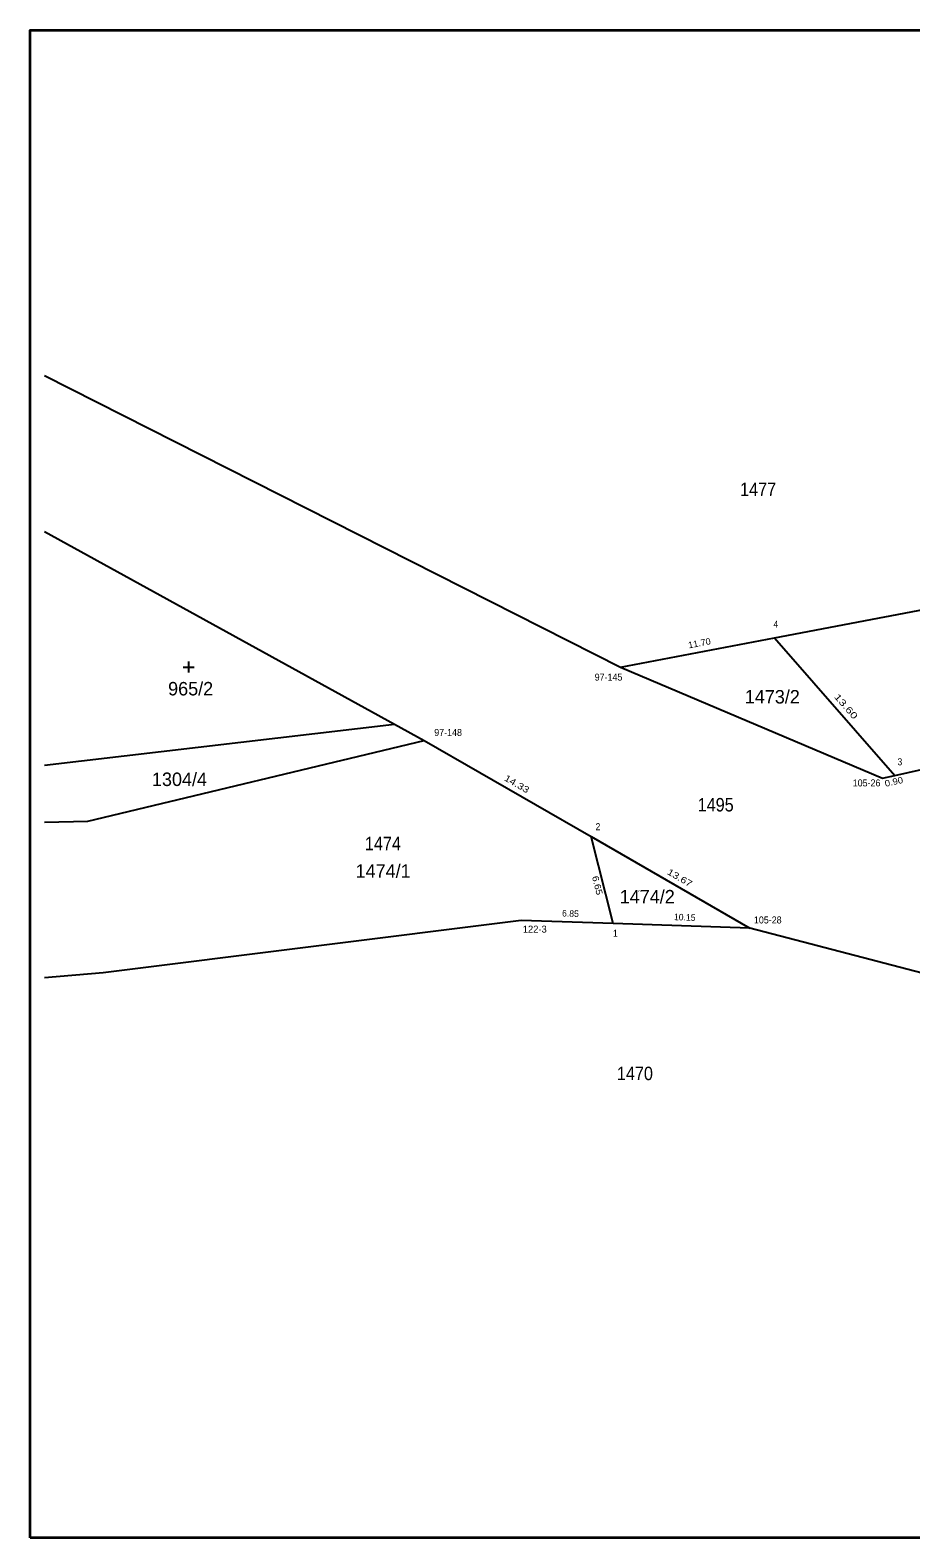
# Model space of a CAD drawing. Extents: x -871901 to -870967, y -1075952 to -1074892.
# Drawn here: x -871449.3 to -871383.9, y -1075118.4 to -1075006.4 of the extents above; entities that cross this region are included whole.
import ezdxf
from ezdxf.enums import TextEntityAlignment as Align

# ---------------------------------------------------------------- set-up
doc = ezdxf.new("R2010")
doc.units = 0
doc.header["$LTSCALE"] = 0.4
for name, color, linetype, lineweight in [('1', 7, 'Continuous', 25), ('25', 7, 'Continuous', 25), ('55', 7, 'Continuous', 35), ('62', 7, 'Continuous', 25)]:
    doc.layers.add(name, color=color, linetype=linetype, lineweight=lineweight)
doc.layers.add('18', color=7, linetype='Continuous')
doc.layers.add('54', color=7, linetype='Continuous')

msp = doc.modelspace()

# ---------------------------------------------------------------- linework, layer by layer
at = {"layer": '1'}
for p, q in [((-871448.26, -1075032.02), (-871405.48, -1075053.67)), ((-871448.26, -1075043.6), (-871422.26, -1075057.91)), ((-871405.48, -1075053.67), (-871386.01, -1075061.93)), ((-871385.08, -1075061.72), (-871352.22, -1075054.34)), ((-871448.26, -1075060.97), (-871422.26, -1075057.91)), ((-871422.26, -1075057.91), (-871420.07, -1075059.12)), ((-871445.05, -1075065.11), (-871420.07, -1075059.12)), ((-871420.07, -1075059.12), (-871407.66, -1075066.26)), ((-871386.01, -1075061.93), (-871385.08, -1075061.72)), ((-871448.26, -1075065.19), (-871445.05, -1075065.11)), ((-871407.66, -1075066.26), (-871395.86, -1075073.06)), ((-871395.86, -1075073.06), (-871406.02, -1075072.72)), ((-871380.21, -1075077.17), (-871395.86, -1075073.06))]:
    msp.add_line(p, q, dxfattribs=at)
for points in [[(-871405.48, -1075053.67), (-871394.04, -1075051.49), (-871345.38, -1075042.25)], [(-871406.02, -1075072.72), (-871412.84, -1075072.49), (-871443.91, -1075076.38), (-871448.26, -1075076.75)]]:
    msp.add_lwpolyline(points, dxfattribs=at)
at = {"layer": '25'}
for p, q in [((-871437.55, -1075054.07), (-871437.55, -1075053.269)), ((-871437.95, -1075053.669), (-871437.149, -1075053.669))]:
    msp.add_line(p, q, dxfattribs=at)
at = {"layer": '55'}
msp.add_lwpolyline([(-871449.33, -1075118.36), (-871449.33, -1075006.36), (-871287.33, -1075006.36), (-871287.33, -1075118.36)], close=True, dxfattribs=at)
at = {"layer": '62'}
for p, q in [((-871394.04, -1075051.49), (-871385.08, -1075061.72)), ((-871406.02, -1075072.72), (-871407.66, -1075066.26))]:
    msp.add_line(p, q, dxfattribs=at)

# ---------------------------------------------------------------- texts
at = {"layer": '18', "width": 0.9}
for s, p in [('1477', (-871396.59, -1075040.97)), ('1495', (-871399.74, -1075064.4)), ('1474', (-871424.46, -1075067.28)), ('1470', (-871405.74, -1075084.36))]:
    msp.add_text(s, height=1, dxfattribs=at).set_placement(p)
at = {"layer": '18'}
for s, p in [('965/2', (-871439.08, -1075055.78)), ('1304/4', (-871440.28, -1075062.51))]:
    msp.add_text(s, height=1, dxfattribs=at).set_placement(p)
at = {"layer": '54'}
for s, width, p in [('4', 0.9, (-871394.11, -1075050.75)), ('97-145', 0.95, (-871407.39, -1075054.68)), ('97-148', 0.95, (-871419.31, -1075058.79)), ('3', 0.9, (-871384.89, -1075060.97)), ('105-26', 0.95, (-871388.22, -1075062.54)), ('2', 0.9, (-871407.32, -1075065.79)), ('105-28', 0.95, (-871395.56, -1075072.72)), ('1', 0.9, (-871406.03, -1075073.71))]:
    msp.add_text(s, height=0.52, dxfattribs=dict(at, width=width)).set_placement(p)
for s, rotation, width, p in [('11.70', 10.7, 1.05, (-871399.5646, -1075052.1326)), ('13.60', 311.202, 1.4, (-871388.8976, -1075056.7519)), ('14.33', 330.003, 1.25, (-871413.2965, -1075062.5627)), ('0.90', 12.6, 1.1, (-871385.1114, -1075062.4242)), ('13.67', 330.003, 1.25, (-871401.1865, -1075069.5327)), ('6.65', 284.202, 1.15, (-871407.4194, -1075069.9506))]:
    msp.add_text(s, height=0.48, rotation=rotation, dxfattribs=dict(at, width=width)).set_placement(p, align=Align.CENTER)
for s, p in [('6.85', (-871409.1974, -1075072.2178)), ('10.15', (-871400.7074, -1075072.4983))]:
    msp.add_text(s, height=0.48, rotation=358.003, dxfattribs=at).set_placement(p, align=Align.CENTER)
msp.add_text('122-3', height=0.52, dxfattribs=at).set_placement((-871412.73, -1075073.4))
at = {"layer": '62'}
for s, height, p in [('1473/2', 1, (-871396.24, -1075056.38)), ('1474/1', 1, (-871425.15, -1075069.32)), ('1474/2', 0.1, (-871404.24, -1075070.37))]:
    msp.add_text(s, height=height, dxfattribs=at).set_placement(p)
msp.add_text('1474/2', height=1, dxfattribs=at).set_placement((-871401.44, -1075071.23), align=Align.RIGHT)

doc.saveas('drawing.dxf')
